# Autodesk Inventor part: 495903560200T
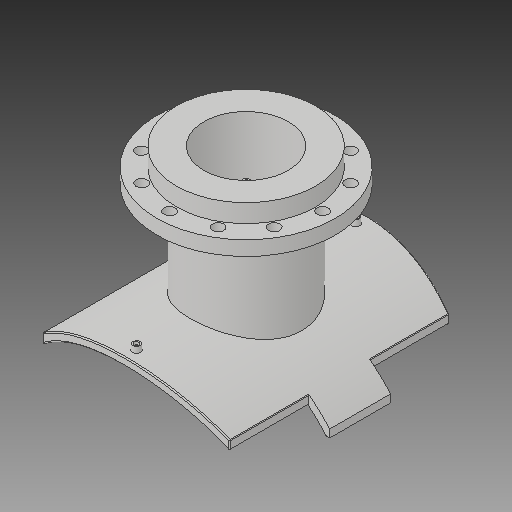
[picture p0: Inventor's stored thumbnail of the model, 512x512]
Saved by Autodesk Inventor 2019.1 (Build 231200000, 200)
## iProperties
Created: 2017-10
Part Number: 495903560200T
Material: Generic
Description: PLASSON FLANGED BRANCH SADDLE 560X200
Document SubType Name: Modeling
Designer: KIM
Mass: 2339.99 g
Surface Area: 3251.55 cm^2
Volume: 2339.99 cm^3
Density: 1 g/cm^3
Appearance: Default
Author: KIM
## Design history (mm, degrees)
derived "495904_495903.ipt"
feature "Solid1::495904_495903.ipt"
feature "Solid2::495904_495903.ipt"
tag "TaggingFeature1"
body "Solid1"
other parameters: "d1" = 15, "d4" = 0, "d6" = 117.5, "d7" = 0, "d12" = 305.6, "d13" = 14, "d14" = 211.5, "d16" = 5 deg, "d18" = 4, "d19" = 14, "d20" = 0, "d21" = 3, "d22" = 0, "d23" = 545, "d36" = 211.5, "d38" = 0, "d39" = 2, "d41" = 163, "d42" = 268, "d43" = 344, "d46" = 214.4, "d47" = 16, "d48" = 10.4, "d49" = 175, "d51" = 571.2, "d53" = 0, "d54" = 22, "d55" = 147.5, "d57" = 0, "d59" = 360 deg, "d61" = 28, "d63" = 0, "d67" = 15, "d68" = 125, "d70" = 0, "d71" = 2, "d_1" = 268, "x_" = 15, "D_" = 16, "DN_" = 163, "D_1" = 344, "t_" = 28, "s_" = 22, "Dp_" = 295
